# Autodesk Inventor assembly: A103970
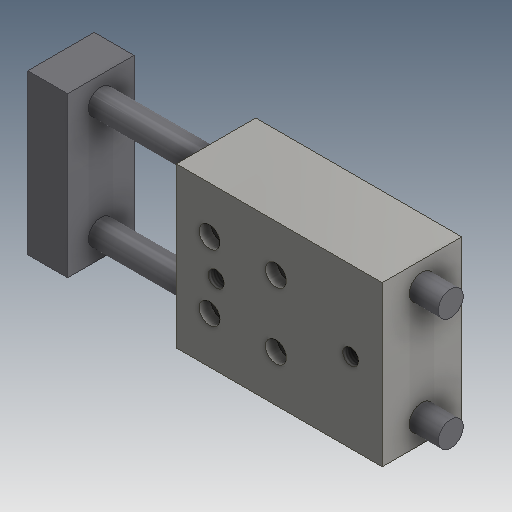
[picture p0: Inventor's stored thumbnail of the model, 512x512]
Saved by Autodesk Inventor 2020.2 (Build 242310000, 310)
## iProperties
Created: 2000-01
Part Number: A103970
Document SubType Name: Assembly
Designer: sspink
Mass: 1344.29 g
Surface Area: 614.964 cm^2
Volume: 338.202 cm^3
Density: 3.97482 g/cm^3
Control State: 0
Checked Out: False
Master: False
Shininess: 0.0
Length Units: 11269
Angle Units: 11279
Time Units: 11290
Mass Units: 11283
Length Display Precision: 3
Angle Display Precision: 2
Compacted: True
Dimensions: 76,2x38x186,3 mm
Mass: 1,344 kg
DocNumber: A103970.iam
Folder: 01 - Themengebiete\Simplification\01 - Packaging machine\
VDS_Category: 3D Komponenten
Density: 0.0
Volumn: 0.0
Area: 0.0
PropertySet Name: Model Information
Author: sspink
Revision Number: -
Title: zylinder
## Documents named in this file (3)
- D:\07 - DEMODATEN\OTX 2019 - Dataset - UPDATE - Dez2019\Designs\07-Packing machine\A103970.iam
- D:\07 - DEMODATEN\OTX 2019 - Dataset - UPDATE - Dez2019\Designs\07-Packing machine\Parts\ADSK-011770.ipt
- D:\07 - DEMODATEN\OTX 2019 - Dataset - UPDATE - Dez2019\Designs\07-Packing machine\Parts\ADSK-011769.ipt
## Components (2 placed, 2 different names)
1. ADSK-011769:1 — Mate:1, Mate:2, stroke
2. ADSK-011770:1 — Mate:1, Mate:2, stroke
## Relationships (3: Mate 2, Flush 1)
- Mate:1: ADSK-011769:1 ↔ ADSK-011770:1
- Mate:2: ADSK-011769:1 ↔ ADSK-011770:1
- stroke [Flush]: ADSK-011769:1 ↔ ADSK-011770:1
